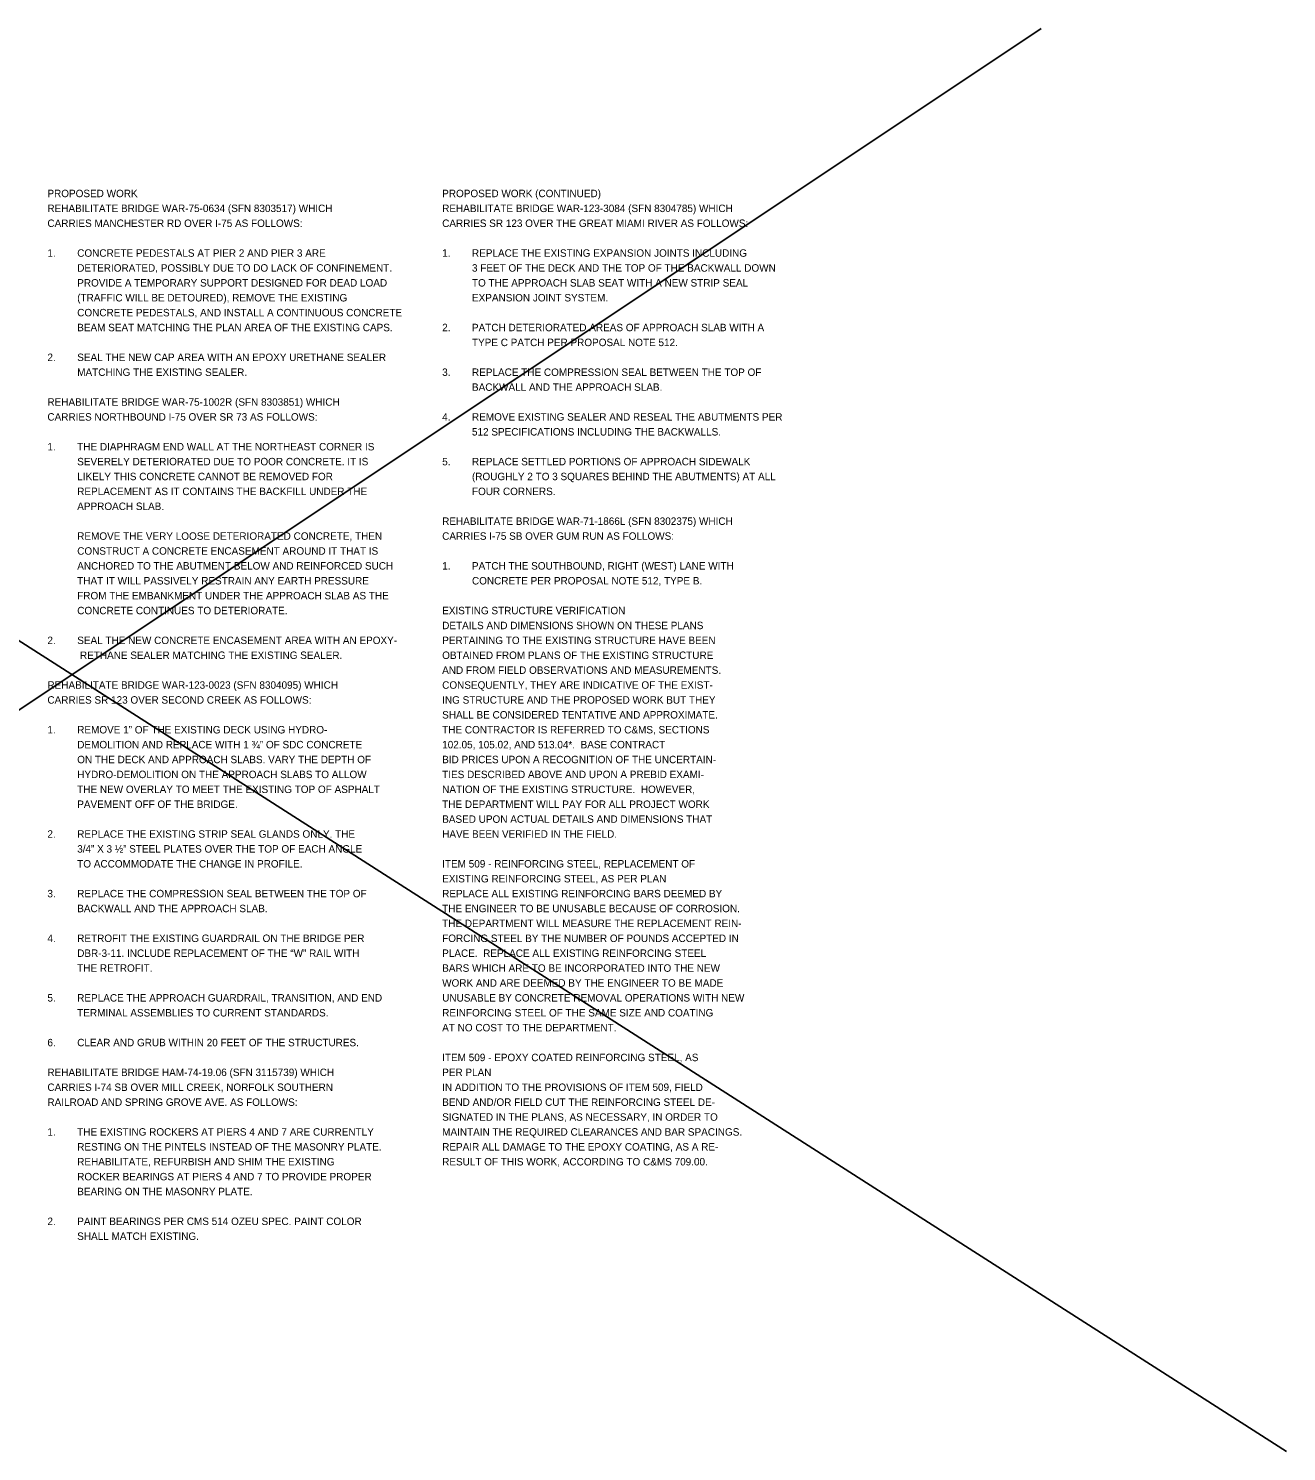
# Model space of a CAD drawing. Extents: x -11.4 to 74.5, y -13.7 to 46.2.
# Drawn here: x 50.88 to 74.53, y 19.42 to 46.17 of the extents above; entities that cross this region are included whole.
import ezdxf

# ---------------------------------------------------------------- set-up
doc = ezdxf.new("R2010")
doc.units = 0
doc.layers.add('Default', color=7, linetype='Continuous')
doc.layers.add('SH_Text', color=7, linetype='Continuous')

msp = doc.modelspace()

# ---------------------------------------------------------------- linework, layer by layer
at = {"layer": 'Default'}
for p, q in [((69.917, 46.171), (36.4, 23.82)), ((33.96, 45.375), (74.531, 19.422))]:
    msp.add_line(p, q, dxfattribs=at)

# ---------------------------------------------------------------- texts
at = {"layer": 'SH_Text'}
for s, p in [('PROPOSED WORK', (51.24, 43)), ('PROPOSED WORK (CONTINUED)', (58.66, 43)), ('REHABILITATE BRIDGE WAR-75-0634 (SFN 8303517) WHICH ', (51.24, 42.72)), ('REHABILITATE BRIDGE WAR-123-3084 (SFN 8304785) WHICH ', (58.66, 42.72)), ('CARRIES MANCHESTER RD OVER I-75 AS FOLLOWS: ', (51.24, 42.44)), ('CARRIES SR 123 OVER THE GREAT MIAMI RIVER AS FOLLOWS:', (58.66, 42.44)), ('1.', (51.24, 41.88)), ('CONCRETE PEDESTALS AT PIER 2 AND PIER 3 ARE', (51.8, 41.88)), ('1.', (58.66, 41.88)), ('REPLACE THE EXISTING EXPANSION JOINTS INCLUDING', (59.22, 41.88)), ('DETERIORATED, POSSIBLY DUE TO DO LACK OF CONFINEMENT.', (51.8, 41.6)), ('3 FEET OF THE DECK AND THE TOP OF THE BACKWALL DOWN', (59.22, 41.6)), ('PROVIDE A TEMPORARY SUPPORT DESIGNED FOR DEAD LOAD', (51.8, 41.32)), ('TO THE APPROACH SLAB SEAT WITH A NEW STRIP SEAL', (59.22, 41.32)), ('(TRAFFIC WILL BE DETOURED), REMOVE THE EXISTING', (51.8, 41.04)), ('EXPANSION JOINT SYSTEM. ', (59.22, 41.04)), ('CONCRETE PEDESTALS, AND INSTALL A CONTINUOUS CONCRETE', (51.8, 40.76)), ('BEAM SEAT MATCHING THE PLAN AREA OF THE EXISTING CAPS.', (51.8, 40.48)), ('2.', (58.66, 40.48)), ('PATCH DETERIORATED AREAS OF APPROACH SLAB WITH A', (59.22, 40.48)), ('TYPE C PATCH PER PROPOSAL NOTE 512. ', (59.22, 40.2)), ('2.', (51.24, 39.92)), ('SEAL THE NEW CAP AREA WITH AN EPOXY URETHANE SEALER', (51.8, 39.92)), ('MATCHING THE EXISTING SEALER.', (51.8, 39.64)), ('3.', (58.66, 39.64)), ('REPLACE THE COMPRESSION SEAL BETWEEN THE TOP OF', (59.22, 39.64)), ('BACKWALL AND THE APPROACH SLAB.', (59.22, 39.36)), ('REHABILITATE BRIDGE WAR-75-1002R (SFN 8303851) WHICH ', (51.24, 39.08)), ('CARRIES NORTHBOUND I-75 OVER SR 73 AS FOLLOWS: ', (51.24, 38.8)), ('4.', (58.66, 38.8)), ('REMOVE EXISTING SEALER AND RESEAL THE ABUTMENTS PER', (59.22, 38.8)), ('512 SPECIFICATIONS INCLUDING THE BACKWALLS.', (59.22, 38.52)), ('1.', (51.24, 38.24)), ('THE DIAPHRAGM END WALL AT THE NORTHEAST CORNER IS', (51.8, 38.24)), ('SEVERELY DETERIORATED DUE TO POOR CONCRETE. IT IS', (51.8, 37.96)), ('5.', (58.66, 37.96)), ('REPLACE SETTLED PORTIONS OF APPROACH SIDEWALK', (59.22, 37.96)), ('LIKELY THIS CONCRETE CANNOT BE REMOVED FOR', (51.8, 37.68)), ('(ROUGHLY 2 TO 3 SQUARES BEHIND THE ABUTMENTS) AT ALL', (59.22, 37.68)), ('REPLACEMENT AS IT CONTAINS THE BACKFILL UNDER THE', (51.8, 37.4)), ('FOUR CORNERS. ', (59.22, 37.4)), ('APPROACH SLAB. ', (51.8, 37.12)), ('REHABILITATE BRIDGE WAR-71-1866L (SFN 8302375) WHICH ', (58.66, 36.84)), ('REMOVE THE VERY LOOSE DETERIORATED CONCRETE, THEN', (51.8, 36.56)), ('CARRIES I-75 SB OVER GUM RUN AS FOLLOWS:', (58.66, 36.56)), ('CONSTRUCT A CONCRETE ENCASEMENT AROUND IT THAT IS', (51.8, 36.28)), ('ANCHORED TO THE ABUTMENT BELOW AND REINFORCED SUCH', (51.8, 36)), ('1.', (58.66, 36)), ('PATCH THE SOUTHBOUND, RIGHT (WEST) LANE WITH', (59.22, 36)), ('THAT IT WILL PASSIVELY RESTRAIN ANY EARTH PRESSURE', (51.8, 35.72)), ('CONCRETE PER PROPOSAL NOTE 512, TYPE B.', (59.22, 35.72)), ('FROM THE EMBANKMENT UNDER THE APPROACH SLAB AS THE', (51.8, 35.44)), ('CONCRETE CONTINUES TO DETERIORATE.', (51.8, 35.16)), ('EXISTING STRUCTURE VERIFICATION', (58.66, 35.16)), ('DETAILS AND DIMENSIONS SHOWN ON THESE PLANS', (58.66, 34.88)), ('2.', (51.24, 34.6)), ('SEAL THE NEW CONCRETE ENCASEMENT AREA WITH AN EPOXY-', (51.8, 34.6)), ('PERTAINING TO THE EXISTING STRUCTURE HAVE BEEN', (58.66, 34.6)), (' RETHANE SEALER MATCHING THE EXISTING SEALER.', (51.8, 34.32)), ('OBTAINED FROM PLANS OF THE EXISTING STRUCTURE', (58.66, 34.32)), ('AND FROM FIELD OBSERVATIONS AND MEASUREMENTS.', (58.66, 34.04)), ('REHABILITATE BRIDGE WAR-123-0023 (SFN 8304095) WHICH ', (51.24, 33.76)), ('CONSEQUENTLY, THEY ARE INDICATIVE OF THE EXIST-', (58.66, 33.76)), ('CARRIES SR 123 OVER SECOND CREEK AS FOLLOWS:', (51.24, 33.48)), ('ING STRUCTURE AND THE PROPOSED WORK BUT THEY', (58.66, 33.48)), ('SHALL BE CONSIDERED TENTATIVE AND APPROXIMATE.', (58.66, 33.2)), ('1.', (51.24, 32.92)), ('REMOVE 1” OF THE EXISTING DECK USING HYDRO-', (51.8, 32.92)), ('THE CONTRACTOR IS REFERRED TO C&MS, SECTIONS', (58.66, 32.92)), ('DEMOLITION AND REPLACE WITH 1 ¾” OF SDC CONCRETE', (51.8, 32.64)), ('102.05, 105.02, AND 513.04*.  BASE CONTRACT', (58.66, 32.64)), ('ON THE DECK AND APPROACH SLABS. VARY THE DEPTH OF', (51.8, 32.36)), ('BID PRICES UPON A RECOGNITION OF THE UNCERTAIN-', (58.66, 32.36)), ('HYDRO-DEMOLITION ON THE APPROACH SLABS TO ALLOW', (51.8, 32.08)), ('TIES DESCRIBED ABOVE AND UPON A PREBID EXAMI-', (58.66, 32.08)), ('THE NEW OVERLAY TO MEET THE EXISTING TOP OF ASPHALT', (51.8, 31.8)), ('NATION OF THE EXISTING STRUCTURE.  HOWEVER,', (58.66, 31.8)), ('PAVEMENT OFF OF THE BRIDGE. ', (51.8, 31.52)), ('THE DEPARTMENT WILL PAY FOR ALL PROJECT WORK', (58.66, 31.52)), ('BASED UPON ACTUAL DETAILS AND DIMENSIONS THAT', (58.66, 31.24)), ('2.', (51.24, 30.96)), ('REPLACE THE EXISTING STRIP SEAL GLANDS ONLY. THE', (51.8, 30.96)), ('HAVE BEEN VERIFIED IN THE FIELD.', (58.66, 30.96)), ('3/4” X 3 ½” STEEL PLATES OVER THE TOP OF EACH ANGLE', (51.8, 30.68)), ('TO ACCOMMODATE THE CHANGE IN PROFILE. ', (51.8, 30.4)), ('ITEM 509 - REINFORCING STEEL, REPLACEMENT OF', (58.66, 30.4)), ('EXISTING REINFORCING STEEL, AS PER PLAN', (58.66, 30.12)), ('3.', (51.24, 29.84)), ('REPLACE THE COMPRESSION SEAL BETWEEN THE TOP OF', (51.8, 29.84)), ('REPLACE ALL EXISTING REINFORCING BARS DEEMED BY', (58.66, 29.84)), ('BACKWALL AND THE APPROACH SLAB.', (51.8, 29.56)), ('THE ENGINEER TO BE UNUSABLE BECAUSE OF CORROSION.', (58.66, 29.56)), ('THE DEPARTMENT WILL MEASURE THE REPLACEMENT REIN-', (58.66, 29.28)), ('4.', (51.24, 29)), ('RETROFIT THE EXISTING GUARDRAIL ON THE BRIDGE PER', (51.8, 29)), ('FORCING STEEL BY THE NUMBER OF POUNDS ACCEPTED IN', (58.66, 29)), ('DBR-3-11. INCLUDE REPLACEMENT OF THE “W” RAIL WITH', (51.8, 28.72)), ('PLACE.  REPLACE ALL EXISTING REINFORCING STEEL', (58.66, 28.72)), ('THE RETROFIT.', (51.8, 28.44)), ('BARS WHICH ARE TO BE INCORPORATED INTO THE NEW', (58.66, 28.44)), ('WORK AND ARE DEEMED BY THE ENGINEER TO BE MADE', (58.66, 28.16)), ('5.', (51.24, 27.88)), ('REPLACE THE APPROACH GUARDRAIL, TRANSITION, AND END', (51.8, 27.88)), ('UNUSABLE BY CONCRETE REMOVAL OPERATIONS WITH NEW', (58.66, 27.88)), ('TERMINAL ASSEMBLIES TO CURRENT STANDARDS.  ', (51.8, 27.6)), ('REINFORCING STEEL OF THE SAME SIZE AND COATING', (58.66, 27.6)), ('AT NO COST TO THE DEPARTMENT.', (58.66, 27.32)), ('6.', (51.24, 27.04)), ('CLEAR AND GRUB WITHIN 20 FEET OF THE STRUCTURES.', (51.8, 27.04)), ('ITEM 509 - EPOXY COATED REINFORCING STEEL, AS', (58.66, 26.76)), ('REHABILITATE BRIDGE HAM-74-19.06 (SFN 3115739) WHICH ', (51.24, 26.48)), ('PER PLAN', (58.66, 26.48)), ('CARRIES I-74 SB OVER MILL CREEK, NORFOLK SOUTHERN', (51.24, 26.2)), ('IN ADDITION TO THE PROVISIONS OF ITEM 509, FIELD', (58.66, 26.2)), ('RAILROAD AND SPRING GROVE AVE. AS FOLLOWS:', (51.24, 25.92)), ('BEND AND/OR FIELD CUT THE REINFORCING STEEL DE-', (58.66, 25.92)), ('SIGNATED IN THE PLANS, AS NECESSARY, IN ORDER TO', (58.66, 25.64)), ('1.', (51.24, 25.36)), ('THE EXISTING ROCKERS AT PIERS 4 AND 7 ARE CURRENTLY', (51.8, 25.36)), ('MAINTAIN THE REQUIRED CLEARANCES AND BAR SPACINGS.', (58.66, 25.36)), ('RESTING ON THE PINTELS INSTEAD OF THE MASONRY PLATE.', (51.8, 25.08)), ('REPAIR ALL DAMAGE TO THE EPOXY COATING, AS A RE-', (58.66, 25.08)), ('REHABILITATE, REFURBISH AND SHIM THE EXISTING', (51.8, 24.8)), ('RESULT OF THIS WORK, ACCORDING TO C&MS 709.00.', (58.66, 24.8)), ('ROCKER BEARINGS AT PIERS 4 AND 7 TO PROVIDE PROPER', (51.8, 24.52)), ('BEARING ON THE MASONRY PLATE. ', (51.8, 24.24)), ('2.', (51.24, 23.68)), ('PAINT BEARINGS PER CMS 514 OZEU SPEC. PAINT COLOR', (51.8, 23.68)), ('SHALL MATCH EXISTING.', (51.8, 23.4))]:
    msp.add_text(s, height=0.14, dxfattribs=at).set_placement(p)

doc.saveas('drawing.dxf')
